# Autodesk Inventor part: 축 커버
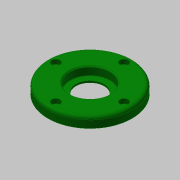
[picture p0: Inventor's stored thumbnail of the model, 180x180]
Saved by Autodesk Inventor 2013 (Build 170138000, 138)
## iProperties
Created: 2015-10
Part Number: 축 커버
Document SubType Name: Modeling
Designer: mdu
Density: 1 g/cm^3
Material: 일반
Mass: 40.8575 g
Surface Area: 133.807 cm^2
Volume: 40.8575 cm^3
Author: mdu
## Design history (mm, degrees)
sketch "스케치1"
  geometry: C1 r 40 at (0, 0) reference; C2 r 26 at (0, 0) reference; 1 further point
  node "참조1"
  node "참조2"
extrude "돌출1" new body sketch "스케치1" distance "d0" = 10; taper "d1" = 0 deg
extrude "돌출2" join sketch "스케치1" distance "d2" = 3; taper "d3" = 0 deg
hole "구멍1" diameter "d6" = 27; stored, may be unused: countersink angle "d10" = 90 deg, drill point angle "d12" = 118 deg; dims "d7" = 6, "d8" = 38, "d9" = 8.3, "d11" = 8, "d31" = 10, "d32" = 10
sketch "스케치2"
  geometry: C1 r 20 at (0, 0); 1 further point
  constraints: 1 centre point, 1 coincident
  dimensions: "d13" = 40 diameter of C1
extrude "돌출3" cut sketch "스케치2" distance "d14" = 3; taper "d15" = 0 deg
sketch "스케치3"
  geometry: C1 r 1.621 at (0, 32.5) reference; 1 further point
hole "구멍2" sketch "스케치3" at (0, 32.5) diameter "d16" = 4.5; stored, may be unused: countersink angle "d20" = 90 deg, drill point angle "d22" = 118 deg; dims "d17" = 6, "d18" = 8, "d19" = 4.4, "d21" = 8
fillet "모깎기1" dims "d26" = 3, "d27" = 0.3
chamfer "모따기1" distance "d28" = 1; stored, may be unused: second distance "d29" = 2, angle "d30" = 45 deg
node "솔리드1"
pattern_circular "원형 패턴1" dims angle "d24" = 360 deg
node "참조3"
